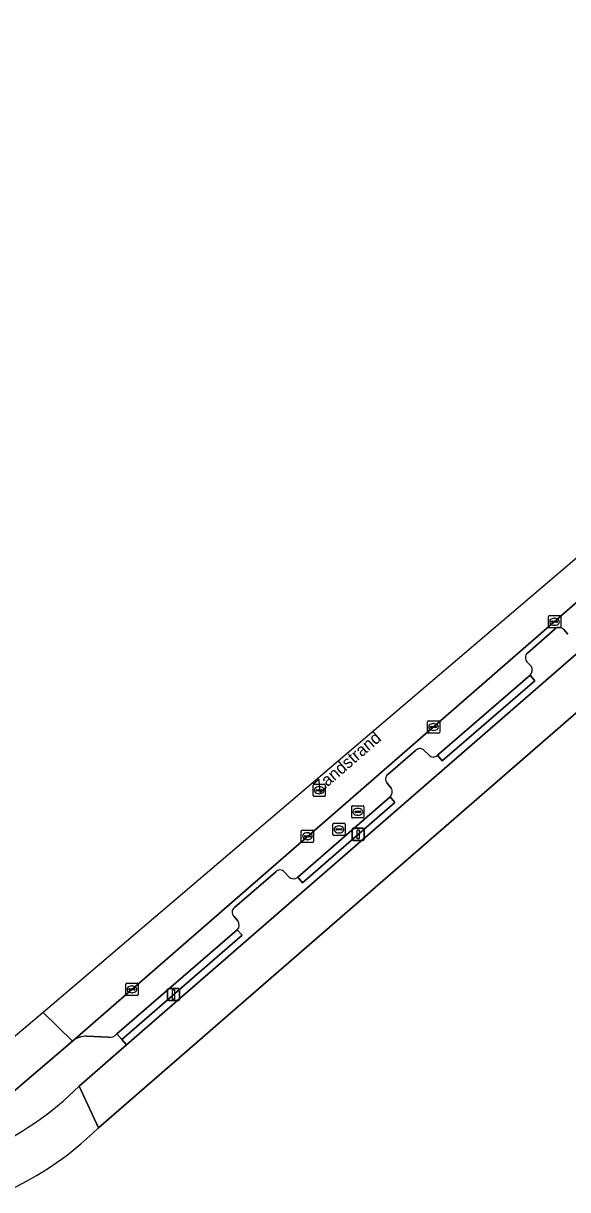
# Model space of a CAD drawing. Extents: x 155640 to 156811, y 382821 to 384049.
# Drawn here: x 156406.4 to 156451, y 383942.1 to 384037.5 of the extents above; entities that cross this region are included whole.
import ezdxf

# ---------------------------------------------------------------- set-up
doc = ezdxf.new("R2010")
doc.units = 0
for name, color, linetype in [('IMGEO_Berm_groen', 7, 'Continuous'), ('IMGEO_Berm_open', 7, 'Continuous'), ('IMGEO_Fietspad_gesloten', 7, 'Continuous'), ('IMGEO_Groenvoorziening', 7, 'Continuous'), ('IMGEO_Kolk', 7, 'Continuous'), ('IMGEO_Lichtmast', 7, 'Continuous'), ('IMGEO_Openbare_ruimte_label', 7, 'Continuous'), ('IMGEO_Parkeervlak_open', 7, 'Continuous'), ('IMGEO_Rijbaan_lokaal_gesloten', 7, 'Continuous'), ('IMGEO_Rioolput', 7, 'Continuous'), ('IMGEO_Verkeerseiland_open', 7, 'Continuous')]:
    doc.layers.add(name, color=color, linetype=linetype)

msp = doc.modelspace()

# ---------------------------------------------------------------- linework, layer by layer
at = {"layer": 'IMGEO_Berm_groen'}
for points in [[(156423.925, 383963.387), (156424.318, 383962.933), (156414.47, 383954.414), (156414.861, 383953.961), (156456.26, 383989.906)], [(156449.952, 383988.008), (156447.687, 383986.029)], [(156450.979, 383987.562), (156450.66, 383987.952)], [(156447.646, 383985.308), (156447.996, 383984.946)], [(156447.898, 383984.213), (156448.29, 383983.759), (156440.715, 383977.209), (156440.323, 383977.663)], [(156438.527, 383978.052), (156436.252, 383976.1)], [(156439.61, 383977.693), (156439.22, 383978.062)], [(156436.198, 383975.388), (156436.521, 383974.98)], [(156436.433, 383974.258), (156436.827, 383973.805), (156429.274, 383967.236), (156428.88, 383967.689)], [(156427.072, 383968.125), (156423.706, 383965.202)], [(156428.138, 383967.709), (156427.779, 383968.123)], [(156423.635, 383964.5), (156423.967, 383964.105)], [(156410.985, 383950.596), (156414.861, 383953.961), (156414.47, 383954.414), (156414.077, 383954.868)], [(156413.339, 383954.6), (156411.614, 383954.679)], [(156410.443, 383954.286), (156406.325, 383950.745), (156404.786, 383949.438)]]:
    msp.add_lwpolyline(points, dxfattribs=at)
for centre, radius, start, end in [((156450.278, 383987.62), 0.506, 40.93925, 130.01584), ((156448.013, 383985.649), 0.501, 130.62046, 222.87025), ((156447.513, 383984.638), 0.573, 312.23297, 32.53679), ((156438.878, 383977.747), 0.465, 42.62481, 139.02863), ((156439.98, 383978.004), 0.484, 220.05517, 315.12615), ((156436.553, 383975.719), 0.486, 128.33312, 222.99256), ((156436.078, 383974.668), 0.542, 310.93137, 35.17035), ((156427.425, 383967.805), 0.476, 41.94298, 137.73286), ((156428.521, 383968.141), 0.577, 228.46232, 308.44971), ((156423.949, 383964.823), 0.45, 122.67621, 225.77333), ((156423.585, 383963.767), 0.51, 311.83835, 41.46616), ((156411.595, 383952.794), 1.885, 89.42774, 127.67686), ((156413.462, 383955.412), 0.821, 261.38744, 318.52889), ((156393.202, 383968.289), 25.085, 271.72451, 315.14534)]:
    msp.add_arc(centre, radius, start, end, dxfattribs=at)
at = {"layer": 'IMGEO_Berm_open'}
for points in [[(156448.29, 383983.759), (156447.898, 383984.213), (156440.323, 383977.663), (156440.715, 383977.209)], [(156424.318, 383962.933), (156423.925, 383963.387), (156414.077, 383954.868), (156414.47, 383954.414)]]:
    msp.add_lwpolyline(points, close=True, dxfattribs=at)
at = {"layer": 'IMGEO_Fietspad_gesloten'}
for points in [[(156491.286, 384020.324), (156490.392, 384019.695), (156467.831, 384000), (156463.665, 383996.347), (156462.195, 383995.059), (156456.26, 383989.906), (156414.861, 383953.961), (156410.985, 383950.596), (156412.558, 383947.186), (156464.513, 383992.278)], [(156412.558, 383947.186), (156410.985, 383950.596)]]:
    msp.add_lwpolyline(points, dxfattribs=at)
for centre, radius, start, end in [((156393.202, 383968.289), 25.085, 271.72451, 315.14534), ((156394.176, 383965.799), 26.16, 269.75761, 314.64317)]:
    msp.add_arc(centre, radius, start, end, dxfattribs=at)
at = {"layer": 'IMGEO_Groenvoorziening'}
msp.add_lwpolyline([(156493.456, 384017.313), (156481.006, 384006.405), (156479.158, 384005), (156473.402, 384000), (156464.513, 383992.278), (156412.558, 383947.186)], dxfattribs=at)
msp.add_arc((156394.176, 383965.799), 26.16, 269.75761, 314.64317, dxfattribs=at)
at = {"layer": 'IMGEO_Kolk'}
for p, q in [((156449.405, 383988.162), (156449.405, 383989.014)), ((156449.48, 383989.088), (156450.332, 383989.088)), ((156449.893, 383988.868), (156449.918, 383988.868)), ((156450.406, 383989.014), (156450.406, 383988.162)), ((156450.332, 383988.088), (156449.48, 383988.088)), ((156449.664, 383988.582), (156449.664, 383988.594)), ((156450.102, 383988.545), (156449.704, 383988.545)), ((156449.707, 383988.631), (156450.105, 383988.631)), ((156449.916, 383988.308), (156449.891, 383988.308)), ((156450.148, 383988.594), (156450.148, 383988.582)), ((156439.498, 383979.551), (156439.498, 383980.403)), ((156439.573, 383980.477), (156440.425, 383980.477)), ((156440.499, 383980.403), (156440.499, 383979.551)), ((156440.425, 383979.477), (156439.573, 383979.477)), ((156439.757, 383979.971), (156439.757, 383979.983)), ((156440.195, 383979.934), (156439.797, 383979.934)), ((156439.8, 383980.02), (156440.198, 383980.02)), ((156440.009, 383979.697), (156439.984, 383979.697)), ((156439.986, 383980.257), (156440.011, 383980.257)), ((156440.241, 383979.983), (156440.241, 383979.971)), ((156429.17, 383970.608), (156429.17, 383971.46)), ((156429.245, 383971.534), (156430.097, 383971.534)), ((156429.429, 383971.028), (156429.429, 383971.04)), ((156429.867, 383970.991), (156429.469, 383970.991)), ((156429.472, 383971.077), (156429.87, 383971.077)), ((156429.681, 383970.754), (156429.656, 383970.754)), ((156429.658, 383971.314), (156429.683, 383971.314)), ((156429.913, 383971.04), (156429.913, 383971.028)), ((156430.171, 383971.46), (156430.171, 383970.608)), ((156430.097, 383970.534), (156429.245, 383970.534)), ((156414.804, 383958.086), (156414.804, 383958.938)), ((156414.879, 383959.012), (156415.731, 383959.012)), ((156415.063, 383958.506), (156415.063, 383958.518)), ((156415.501, 383958.469), (156415.103, 383958.469)), ((156415.106, 383958.555), (156415.504, 383958.555)), ((156415.292, 383958.792), (156415.317, 383958.792)), ((156415.547, 383958.518), (156415.547, 383958.506)), ((156415.805, 383958.938), (156415.805, 383958.086)), ((156415.731, 383958.012), (156414.879, 383958.012)), ((156415.315, 383958.232), (156415.29, 383958.232))]:
    msp.add_line(p, q, dxfattribs=at)
for points in [[(156449.405, 383988.162), (156449.405, 383989.014)], [(156449.48, 383989.088), (156450.332, 383989.088)], [(156450.406, 383989.014), (156450.406, 383988.162)], [(156450.332, 383988.088), (156449.48, 383988.088)], [(156439.498, 383979.551), (156439.498, 383980.403)], [(156439.573, 383980.477), (156440.425, 383980.477)], [(156440.499, 383980.403), (156440.499, 383979.551)], [(156440.425, 383979.477), (156439.573, 383979.477)], [(156429.17, 383970.608), (156429.17, 383971.46)], [(156429.245, 383971.534), (156430.097, 383971.534)], [(156430.171, 383971.46), (156430.171, 383970.608)], [(156430.097, 383970.534), (156429.245, 383970.534)], [(156414.804, 383958.086), (156414.804, 383958.938)], [(156414.879, 383959.012), (156415.731, 383959.012)], [(156415.805, 383958.938), (156415.805, 383958.086)], [(156415.731, 383958.012), (156414.879, 383958.012)]]:
    msp.add_lwpolyline(points, dxfattribs=at)
for centre, radius, start, end in [((156449.482, 383989.012), 0.0765, 91.55205, 178.44795), ((156449.482, 383989.012), 0.0765, 91.55205, 178.44795), ((156450.33, 383989.012), 0.0765, 1.55205, 88.44795), ((156450.33, 383989.012), 0.0765, 1.55205, 88.44795), ((156449.482, 383988.164), 0.0765, 181.55205, 268.44795), ((156449.482, 383988.164), 0.0765, 181.55205, 268.44795), ((156449.704, 383988.591), 0.0403, 85.87752, 175.75265), ((156449.701, 383988.581), 0.0366, 178.93798, 274.71019), ((156450.105, 383988.588), 0.043, 264.86636, 352.45326), ((156450.109, 383988.593), 0.0386, 1.73085, 96.63898), ((156450.33, 383988.164), 0.0765, 271.55205, 358.44795), ((156450.33, 383988.164), 0.0765, 271.55205, 358.44795), ((156439.575, 383980.401), 0.0765, 91.55205, 178.44795), ((156439.575, 383980.401), 0.0765, 91.55205, 178.44795), ((156440.423, 383980.401), 0.0765, 1.55205, 88.44795), ((156440.423, 383980.401), 0.0765, 1.55205, 88.44795), ((156439.575, 383979.553), 0.0765, 181.55205, 268.44795), ((156439.575, 383979.553), 0.0765, 181.55205, 268.44795), ((156439.797, 383979.98), 0.0403, 85.87752, 175.75265), ((156439.794, 383979.97), 0.0366, 178.93798, 274.71019), ((156440.198, 383979.977), 0.043, 264.86636, 352.45326), ((156440.202, 383979.982), 0.0386, 1.73085, 96.63898), ((156440.423, 383979.553), 0.0765, 271.55205, 358.44795), ((156440.423, 383979.553), 0.0765, 271.55205, 358.44795), ((156429.247, 383971.458), 0.0765, 91.55205, 178.44795), ((156429.247, 383971.458), 0.0765, 91.55205, 178.44795), ((156429.469, 383971.037), 0.0403, 85.87752, 175.75265), ((156429.466, 383971.027), 0.0366, 178.93798, 274.71019), ((156429.87, 383971.034), 0.043, 264.86636, 352.45326), ((156429.874, 383971.039), 0.0386, 1.73085, 96.63898), ((156430.095, 383971.458), 0.0765, 1.55205, 88.44795), ((156430.095, 383971.458), 0.0765, 1.55205, 88.44795), ((156429.247, 383970.61), 0.0765, 181.55205, 268.44795), ((156429.247, 383970.61), 0.0765, 181.55205, 268.44795), ((156430.095, 383970.61), 0.0765, 271.55205, 358.44795), ((156430.095, 383970.61), 0.0765, 271.55205, 358.44795), ((156414.881, 383958.936), 0.0765, 91.55205, 178.44795), ((156414.881, 383958.936), 0.0765, 91.55205, 178.44795), ((156415.103, 383958.515), 0.0403, 85.87752, 175.75265), ((156415.1, 383958.505), 0.0366, 178.93798, 274.71019), ((156415.504, 383958.512), 0.043, 264.86636, 352.45326), ((156415.508, 383958.517), 0.0386, 1.73085, 96.63898), ((156415.729, 383958.936), 0.0765, 1.55205, 88.44795), ((156415.729, 383958.936), 0.0765, 1.55205, 88.44795), ((156414.881, 383958.088), 0.0765, 181.55205, 268.44795), ((156414.881, 383958.088), 0.0765, 181.55205, 268.44795), ((156415.729, 383958.088), 0.0765, 271.55205, 358.44795), ((156415.729, 383958.088), 0.0765, 271.55205, 358.44795)]:
    msp.add_arc(centre, radius, start, end, dxfattribs=at)
for centre, major_axis, ratio, start_param, end_param in [((156449.892, 383988.588), (-0.387, 0.002), 0.722429, 4.712389, 7.853982), ((156449.917, 383988.588), (-0.39, 0.002), 0.717154, 1.570796, 4.712389), ((156439.985, 383979.977), (-0.387, 0.002), 0.722429, 4.712389, 7.853982), ((156440.01, 383979.977), (-0.39, 0.002), 0.717154, 1.570796, 4.712389), ((156429.657, 383971.034), (-0.387, 0.002), 0.722429, 4.712389, 7.853982), ((156429.682, 383971.034), (-0.39, 0.002), 0.717154, 1.570796, 4.712389), ((156415.291, 383958.512), (-0.387, 0.002), 0.722429, 4.712389, 7.853982), ((156415.316, 383958.512), (-0.39, 0.002), 0.717154, 1.570796, 4.712389)]:
    msp.add_ellipse(centre, major_axis=major_axis, ratio=ratio, start_param=start_param, end_param=end_param, dxfattribs=at)
at = {"layer": 'IMGEO_Lichtmast'}
for p, q in [((156433.429, 383971.698), (156434.219, 383971.698)), ((156434.219, 383971.698), (156433.429, 383971.698)), ((156433.329, 383970.798), (156433.329, 383971.598)), ((156433.329, 383971.598), (156433.329, 383970.798)), ((156434.319, 383971.598), (156434.319, 383970.798)), ((156434.319, 383970.798), (156434.319, 383971.598)), ((156434.219, 383970.698), (156433.429, 383970.698)), ((156433.429, 383970.698), (156434.219, 383970.698)), ((156418.218, 383957.694), (156418.218, 383958.494)), ((156418.218, 383958.494), (156418.218, 383957.694)), ((156418.318, 383958.594), (156419.108, 383958.594)), ((156419.108, 383958.594), (156418.318, 383958.594)), ((156419.208, 383958.494), (156419.208, 383957.694)), ((156419.208, 383957.694), (156419.208, 383958.494)), ((156419.108, 383957.594), (156418.318, 383957.594)), ((156418.318, 383957.594), (156419.108, 383957.594))]:
    msp.add_line(p, q, dxfattribs=at)
for points in [[(156433.749, 383971.573), (156433.899, 383971.573), (156433.899, 383970.823), (156433.749, 383970.823), (156433.749, 383971.573)], [(156418.638, 383958.469), (156418.788, 383958.469), (156418.788, 383957.719), (156418.638, 383957.719), (156418.638, 383958.469)]]:
    msp.add_lwpolyline(points, dxfattribs=at)
for centre, start, end in [((156433.429, 383971.598), 90, 180), ((156433.429, 383971.598), 90, 180), ((156434.219, 383971.598), 0, 90), ((156434.219, 383971.598), 360, 90), ((156433.429, 383970.798), 180, 270), ((156433.429, 383970.798), 180, 270), ((156434.219, 383970.798), 270, 0), ((156434.219, 383970.798), 270, 0), ((156418.318, 383958.494), 90, 180), ((156418.318, 383958.494), 90, 180), ((156419.108, 383958.494), 0, 90), ((156419.108, 383958.494), 360, 90), ((156418.318, 383957.694), 180, 270), ((156418.318, 383957.694), 180, 270), ((156419.108, 383957.694), 270, 0), ((156419.108, 383957.694), 270, 0)]:
    msp.add_arc(centre, 0.1, start, end, dxfattribs=at)
at = {"layer": 'IMGEO_Parkeervlak_open'}
for points in [[(156492.381, 384025.493), (156463.008, 384000), (156459.568, 383997.014), (156410.443, 383954.286)], [(156447.687, 383986.029), (156449.952, 383988.008)], [(156450.66, 383987.952), (156450.979, 383987.562)], [(156447.996, 383984.946), (156447.646, 383985.308)], [(156440.323, 383977.663), (156447.898, 383984.213)], [(156436.252, 383976.1), (156438.527, 383978.052)], [(156439.22, 383978.062), (156439.61, 383977.693)], [(156436.521, 383974.98), (156436.198, 383975.388)], [(156428.88, 383967.689), (156436.433, 383974.258)], [(156423.706, 383965.202), (156427.072, 383968.125)], [(156427.779, 383968.123), (156428.138, 383967.709)], [(156423.967, 383964.105), (156423.635, 383964.5)], [(156414.077, 383954.868), (156423.925, 383963.387)], [(156411.614, 383954.679), (156413.339, 383954.6)]]:
    msp.add_lwpolyline(points, dxfattribs=at)
for centre, radius, start, end in [((156450.278, 383987.62), 0.506, 40.93925, 130.01584), ((156448.013, 383985.649), 0.501, 130.62046, 222.87025), ((156447.513, 383984.638), 0.573, 312.23297, 32.53679), ((156438.878, 383977.747), 0.465, 42.62481, 139.02863), ((156439.98, 383978.004), 0.484, 220.05517, 315.12615), ((156436.553, 383975.719), 0.486, 128.33312, 222.99256), ((156436.078, 383974.668), 0.542, 310.93137, 35.17035), ((156427.425, 383967.805), 0.476, 41.94298, 137.73286), ((156428.521, 383968.141), 0.577, 228.46232, 308.44971), ((156423.949, 383964.823), 0.45, 122.67621, 225.77333), ((156423.585, 383963.767), 0.51, 311.83835, 41.46616), ((156411.595, 383952.794), 1.885, 89.42774, 127.67686), ((156413.462, 383955.412), 0.821, 261.38744, 318.52889)]:
    msp.add_arc(centre, radius, start, end, dxfattribs=at)
at = {"layer": 'IMGEO_Rijbaan_lokaal_gesloten'}
for points in [[(156503.1, 384037.543), (156455.868, 383997.337), (156456.798, 383996.277), (156454.172, 383993.966), (156453.209, 383995.074), (156408.038, 383956.623)], [(156408.038, 383956.623), (156410.443, 383954.286), (156459.568, 383997.014), (156463.008, 384000), (156492.381, 384025.493), (156492.482, 384025.587), (156494.22, 384027.084)], [(156404.786, 383949.438), (156406.325, 383950.745), (156410.443, 383954.286), (156408.038, 383956.623), (156405.586, 383954.536), (156394.629, 383945.209)]]:
    msp.add_lwpolyline(points, dxfattribs=at)
at = {"layer": 'IMGEO_Rioolput'}
for p, q in [((156430.133, 383974.373), (156430.133, 383975.225)), ((156430.208, 383975.299), (156431.06, 383975.299)), ((156430.392, 383974.793), (156430.392, 383974.805)), ((156430.83, 383974.756), (156430.432, 383974.756)), ((156430.435, 383974.842), (156430.833, 383974.842)), ((156430.621, 383975.079), (156430.646, 383975.079)), ((156430.876, 383974.805), (156430.876, 383974.793)), ((156431.134, 383975.225), (156431.134, 383974.373)), ((156431.06, 383974.299), (156430.208, 383974.299)), ((156430.644, 383974.519), (156430.619, 383974.519)), ((156433.297, 383972.609), (156433.297, 383973.461)), ((156433.372, 383973.535), (156434.224, 383973.535)), ((156433.556, 383973.029), (156433.556, 383973.041)), ((156433.994, 383972.992), (156433.596, 383972.992)), ((156433.599, 383973.078), (156433.997, 383973.078)), ((156433.808, 383972.755), (156433.783, 383972.755)), ((156433.785, 383973.315), (156433.81, 383973.315)), ((156434.04, 383973.041), (156434.04, 383973.029)), ((156434.298, 383973.461), (156434.298, 383972.609)), ((156431.754, 383971.172), (156431.754, 383972.024)), ((156431.829, 383972.098), (156432.681, 383972.098)), ((156432.242, 383971.878), (156432.267, 383971.878)), ((156432.755, 383972.024), (156432.755, 383971.172)), ((156434.224, 383972.535), (156433.372, 383972.535)), ((156432.681, 383971.098), (156431.829, 383971.098)), ((156432.013, 383971.592), (156432.013, 383971.604)), ((156432.451, 383971.555), (156432.053, 383971.555)), ((156432.056, 383971.641), (156432.454, 383971.641)), ((156432.265, 383971.318), (156432.24, 383971.318)), ((156432.497, 383971.604), (156432.497, 383971.592))]:
    msp.add_line(p, q, dxfattribs=at)
for points in [[(156430.133, 383974.373), (156430.133, 383975.225)], [(156430.208, 383975.299), (156431.06, 383975.299)], [(156431.134, 383975.225), (156431.134, 383974.373)], [(156431.06, 383974.299), (156430.208, 383974.299)], [(156433.297, 383972.609), (156433.297, 383973.461)], [(156433.372, 383973.535), (156434.224, 383973.535)], [(156434.298, 383973.461), (156434.298, 383972.609)], [(156431.754, 383971.172), (156431.754, 383972.024)], [(156431.829, 383972.098), (156432.681, 383972.098)], [(156432.755, 383972.024), (156432.755, 383971.172)], [(156434.224, 383972.535), (156433.372, 383972.535)], [(156432.681, 383971.098), (156431.829, 383971.098)]]:
    msp.add_lwpolyline(points, dxfattribs=at)
for centre, radius, start, end in [((156430.21, 383975.223), 0.0765, 91.55205, 178.44795), ((156430.21, 383975.223), 0.0765, 91.55205, 178.44795), ((156430.432, 383974.802), 0.0403, 85.87752, 175.75265), ((156430.429, 383974.792), 0.0366, 178.93798, 274.71019), ((156430.833, 383974.799), 0.043, 264.86636, 352.45326), ((156430.837, 383974.804), 0.0386, 1.73085, 96.63898), ((156431.058, 383975.223), 0.0765, 1.55205, 88.44795), ((156431.058, 383975.223), 0.0765, 1.55205, 88.44795), ((156430.21, 383974.375), 0.0765, 181.55205, 268.44795), ((156430.21, 383974.375), 0.0765, 181.55205, 268.44795), ((156431.058, 383974.375), 0.0765, 271.55205, 358.44795), ((156431.058, 383974.375), 0.0765, 271.55205, 358.44795), ((156433.374, 383973.459), 0.0765, 91.55205, 178.44795), ((156433.374, 383973.459), 0.0765, 91.55205, 178.44795), ((156433.596, 383973.038), 0.0403, 85.87752, 175.75265), ((156433.593, 383973.028), 0.0366, 178.93798, 274.71019), ((156433.997, 383973.035), 0.043, 264.86636, 352.45326), ((156434.001, 383973.04), 0.0386, 1.73085, 96.63898), ((156434.222, 383973.459), 0.0765, 1.55205, 88.44795), ((156434.222, 383973.459), 0.0765, 1.55205, 88.44795), ((156431.831, 383972.022), 0.0765, 91.55205, 178.44795), ((156431.831, 383972.022), 0.0765, 91.55205, 178.44795), ((156432.679, 383972.022), 0.0765, 1.55205, 88.44795), ((156432.679, 383972.022), 0.0765, 1.55205, 88.44795), ((156433.374, 383972.611), 0.0765, 181.55205, 268.44795), ((156433.374, 383972.611), 0.0765, 181.55205, 268.44795), ((156434.222, 383972.611), 0.0765, 271.55205, 358.44795), ((156434.222, 383972.611), 0.0765, 271.55205, 358.44795), ((156431.831, 383971.174), 0.0765, 181.55205, 268.44795), ((156431.831, 383971.174), 0.0765, 181.55205, 268.44795), ((156432.053, 383971.601), 0.0403, 85.87752, 175.75265), ((156432.05, 383971.591), 0.0366, 178.93798, 274.71019), ((156432.454, 383971.598), 0.043, 264.86636, 352.45326), ((156432.458, 383971.603), 0.0386, 1.73085, 96.63898), ((156432.679, 383971.174), 0.0765, 271.55205, 358.44795), ((156432.679, 383971.174), 0.0765, 271.55205, 358.44795)]:
    msp.add_arc(centre, radius, start, end, dxfattribs=at)
for centre, major_axis, ratio, start_param, end_param in [((156430.62, 383974.799), (-0.387, 0.002), 0.722429, 4.712389, 7.853982), ((156430.645, 383974.799), (-0.39, 0.002), 0.717154, 1.570796, 4.712389), ((156433.784, 383973.035), (-0.387, 0.002), 0.722429, 4.712389, 7.853982), ((156433.809, 383973.035), (-0.39, 0.002), 0.717154, 1.570796, 4.712389), ((156432.241, 383971.598), (-0.387, 0.002), 0.722429, 4.712389, 7.853982), ((156432.266, 383971.598), (-0.39, 0.002), 0.717154, 1.570796, 4.712389)]:
    msp.add_ellipse(centre, major_axis=major_axis, ratio=ratio, start_param=start_param, end_param=end_param, dxfattribs=at)
at = {"layer": 'IMGEO_Verkeerseiland_open'}
msp.add_lwpolyline([(156436.433, 383974.258), (156428.88, 383967.689), (156429.274, 383967.236), (156436.827, 383973.805)], close=True, dxfattribs=at)

# ---------------------------------------------------------------- texts
at = {"layer": 'IMGEO_Openbare_ruimte_label'}
msp.add_text('Zandstrand', height=1, rotation=40.90573, dxfattribs=at).set_placement((156430.69, 383974.512))

doc.saveas('drawing.dxf')
